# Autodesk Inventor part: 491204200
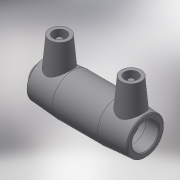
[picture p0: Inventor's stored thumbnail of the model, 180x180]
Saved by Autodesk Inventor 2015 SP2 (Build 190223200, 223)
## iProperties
Created: 2017-06
Part Number: 491204200
Material: Generic
Description: PLASSON END CAP 200
Document SubType Name: Modeling
Designer: KIM
Mass: 38.9236 g
Surface Area: 152.394 cm^2
Volume: 38.9236 cm^3
Density: 1 g/cm^3
Appearance: Default
Author: KIM
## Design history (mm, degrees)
derived "491204.ipt"
feature "Solid1::491204.ipt"
tag "TaggingFeature1"
body "Solid1"
other parameters: "d0" = 223, "d2" = 242, "d3" = 109, "d4" = 72.25, "d5" = 217.8, "d8" = 168 deg, "d10" = 43.6, "d11" = 14.53333, "d13" = 231.2, "d14" = 17.6296, "d15" = 109, "d16" = 109, "d19" = 3.52592, "d20" = 168 deg, "d22" = 227.48, "d23" = 242, "d24" = 220.6556, "d25" = 135 deg, "d26" = 104.04, "d27" = 135 deg, "d29" = 126, "d30" = 15, "d31" = 92.48, "d34" = 5 deg, "d35" = 15, "d39" = 5 deg, "d41" = 4, "d42" = 14, "d43" = 0, "d45" = 4, "d46" = 14, "d47" = 0, "d48" = 289, "d49" = 1, "d52" = 5.202, "d54" = 5.202, "d57" = 6, "d60" = 43.35, "d61" = 4, "d63" = 289, "d64" = 1, "d69" = 5.78, "d70" = 0, "d71" = 5.202, "d72" = 3, "d73" = 0, "d74" = 31.61, "d75" = 10.53667, "d76" = 3, "d77" = 0, "L_" = 289, "L_1" = 109, "D_" = 242, "A_" = 126, "d_2" = 12, "L_0" = 223
